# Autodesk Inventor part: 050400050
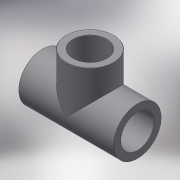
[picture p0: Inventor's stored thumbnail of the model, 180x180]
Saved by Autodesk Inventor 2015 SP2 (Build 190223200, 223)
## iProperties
Created: 2017-10
Part Number: 050400050
Material: Generic
Description: PLASSON TEE-CEMENT PVC 50
Document SubType Name: Modeling
Designer: KIM
Density: 1 g/cm^3
Appearance: Default
Author: KIM
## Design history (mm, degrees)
derived "050400.ipt"
feature "Solid1::050400.ipt"
feature "Solid2::050400.ipt"
tag "TaggingFeature1"
body "Solid1"
other parameters: "d0" = 118, "d1" = 62, "d2" = 31, "d5" = 45, "d7" = 0.5, "d8" = 31, "d9" = 59, "d10" = 62, "d12" = 45, "d15" = 0, "d17" = 0, "d19" = 45, "d21" = 31, "d22" = 0, "d23" = 31, "d24" = 0.5, "E_" = 62, "H_" = 118, "l_" = 31, "Z_" = 28
